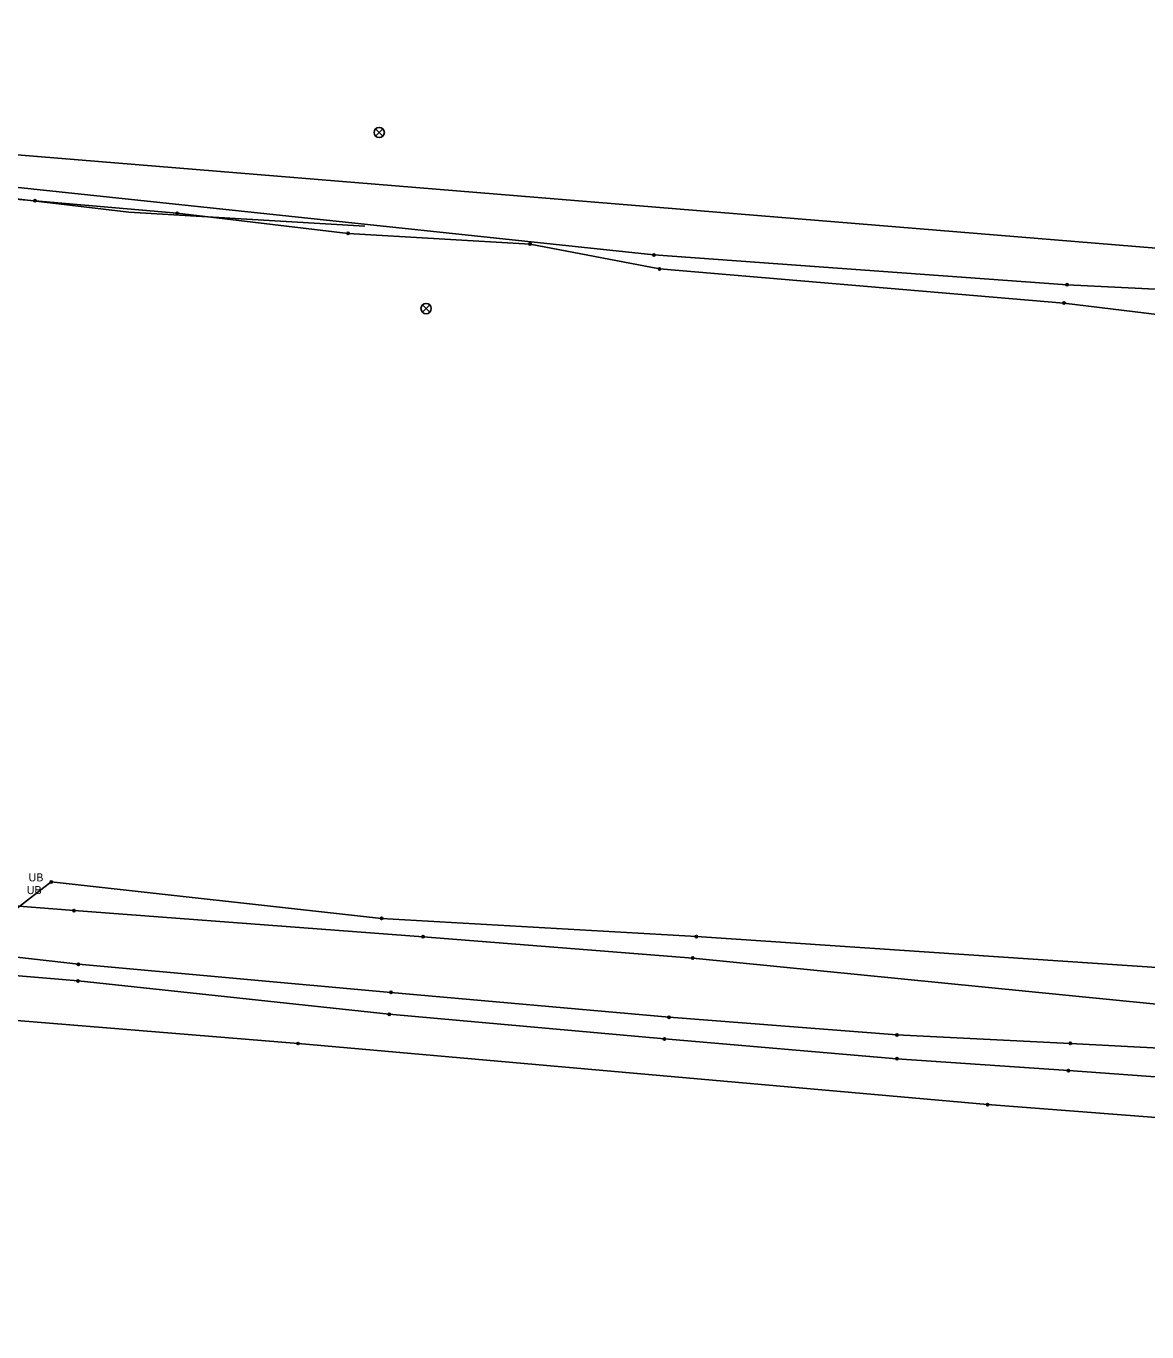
# Model space of a CAD drawing. Extents: x 20500343 to 20505311, y 7953484 to 7954193.
# Drawn here: x 20503191.9 to 20503387.9, y 7953635.3 to 7953863.5 of the extents above; entities that cross this region are included whole.
import ezdxf

# ---------------------------------------------------------------- set-up
doc = ezdxf.new("R2010")
doc.units = 0
for name, color, linetype in [('C-PROP-LINE-LOT', 7, 'Continuous'), ('V-ANNO-BNDY', 7, 'Continuous'), ('V-ANNO-NOTE', 7, 'Continuous'), ('V-SITE-FENC', 7, 'Continuous'), ('V-SSWR-STRC', 7, 'Continuous')]:
    doc.layers.add(name, color=color, linetype=linetype)

msp = doc.modelspace()

# ---------------------------------------------------------------- linework, layer by layer
at = {"layer": 'C-PROP-LINE-LOT'}
msp.add_line((20503185.95, 7953841.37), (20503437.68, 7953820.69), dxfattribs=at)
for points in [[(20502923.89, 7953863.48), (20502923.87, 7953857.22), (20502949.69, 7953853.27), (20502980.21, 7953850.33), (20503012.7, 7953848.26), (20503049, 7953845.63), (20503082.17, 7953842.1), (20503112.95, 7953839.56), (20503138.35, 7953837.73), (20503193.47, 7953832.98), (20503218.34, 7953830.79), (20503248.23, 7953827.27), (20503280.04, 7953825.39), (20503302.66, 7953821.04), (20503373.35, 7953815.08), (20503420.82, 7953809.31), (20503465.76, 7953808.12), (20503523.4, 7953802.43), (20503558.95, 7953800.72), (20503614.46, 7953794.57), (20503665.44, 7953787.94), (20503677.02, 7953787.65), (20503693.06, 7953785.61)], [(20502923.89, 7953863.47), (20502924.73, 7953858.96), (20502949.8, 7953857.13), (20502979.15, 7953855.66), (20503010.57, 7953853.39), (20503049.45, 7953848.56), (20503082.45, 7953846.12), (20503112.47, 7953843.06), (20503138.8, 7953840.76), (20503301.69, 7953823.49), (20503373.91, 7953818.29), (20503420.2, 7953815.98), (20503466.21, 7953810.37), (20503524.2, 7953805.14), (20503558.57, 7953802.46), (20503613.81, 7953798.05), (20503665.73, 7953789.96), (20503676.95, 7953790.93), (20503697.66, 7953791.85), (20503755.76, 7953785.45), (20503787.39, 7953784.49)], [(20503171.09, 7953843.45), (20503173.08, 7953837.17), (20503180.82, 7953834.4), (20503209.91, 7953830.98), (20503251.16, 7953828.52)], [(20502583.99, 7953772.95), (20502610.65, 7953768.87), (20502654.81, 7953765.56), (20502704, 7953762.66), (20502780.84, 7953747.28), (20502856.1, 7953741.6), (20502958.12, 7953733.02), (20503064.96, 7953721.73), (20503167.51, 7953711.49), (20503200.31, 7953708.91), (20503261.33, 7953704.35), (20503308.48, 7953700.62), (20503425.37, 7953689.03), (20503525.59, 7953683.92), (20503632.36, 7953675.44)], [(20502567.82, 7953767.29), (20502613.16, 7953765.86), (20502660.75, 7953761.57), (20502684.96, 7953758.32), (20502704.25, 7953752.73), (20502749.31, 7953741.65), (20502800.87, 7953733.72), (20502861.3, 7953730.84), (20502920.69, 7953724.3), (20502983.15, 7953721.6), (20503039.18, 7953715.3), (20503094.87, 7953710.44), (20503155.33, 7953704.72), (20503201.09, 7953699.55), (20503255.71, 7953694.61), (20503304.33, 7953690.28), (20503344.16, 7953687.19), (20503374.46, 7953685.7), (20503426.83, 7953682.97), (20503524.49, 7953672.95), (20503631.72, 7953664.81)], [(20502567.9, 7953761.34), (20502613.51, 7953762.6), (20502660.72, 7953759.56), (20502684.44, 7953756.31), (20502703.23, 7953750.18), (20502747.73, 7953738.37), (20502800.44, 7953730.37), (20502860.52, 7953724.51), (20502919.86, 7953720.87), (20502983.04, 7953717.79), (20503038.66, 7953709.78), (20503094.29, 7953705.56), (20503153.13, 7953700.69), (20503201.01, 7953696.62), (20503255.42, 7953690.81), (20503303.52, 7953686.48), (20503344.16, 7953683.02), (20503374.14, 7953680.96), (20503426.87, 7953677.14), (20503523.93, 7953669.23), (20503630.84, 7953663.08)], [(20502753.52, 7953725.91), (20502816.21, 7953720.99), (20502880.43, 7953715.32), (20503003.58, 7953704.35), (20503122.54, 7953695.27), (20503239.48, 7953685.69), (20503360, 7953675.01), (20503474.19, 7953666.22), (20503697.41, 7953647.35), (20503810.09, 7953637.77), (20503838.81, 7953635.29)], [(20503189.83, 7953708.93), (20503196.34, 7953713.92), (20503254.07, 7953707.55), (20503309.11, 7953704.37), (20503425.93, 7953696.5), (20503526.62, 7953689.02), (20503632.63, 7953678.56)]]:
    msp.add_lwpolyline(points, dxfattribs=at)
at = {"layer": 'V-ANNO-BNDY'}
msp.add_line((20503223.08, 7953707.22), (20503223.08, 7953707.22), dxfattribs=at)
at = {"layer": 'V-ANNO-NOTE'}
for centre in [(20503193.47, 7953832.98), (20503218.34, 7953830.79), (20503248.23, 7953827.27), (20503280.04, 7953825.39), (20503301.69, 7953823.49), (20503302.66, 7953821.04), (20503373.91, 7953818.29), (20503373.35, 7953815.08), (20503196.34, 7953713.92), (20503200.31, 7953708.91), (20503254.07, 7953707.55), (20503261.33, 7953704.35), (20503309.11, 7953704.37), (20503201.09, 7953699.55), (20503308.48, 7953700.62), (20503201.01, 7953696.62), (20503255.71, 7953694.61), (20503255.42, 7953690.81), (20503304.33, 7953690.28), (20503239.48, 7953685.69), (20503303.52, 7953686.48), (20503344.16, 7953687.19), (20503374.46, 7953685.7), (20503344.16, 7953683.02), (20503374.14, 7953680.96), (20503360, 7953675.01)]:
    msp.add_circle(centre, 0.2, dxfattribs=at)
at = {"layer": 'V-SSWR-STRC'}
for points in [[(20503253.02, 7953844.25), (20503253.66, 7953844.89), (20503253.02, 7953845.52)], [(20503254.3, 7953845.52), (20503253.66, 7953844.89), (20503254.3, 7953844.25)], [(20503261.22, 7953813.49), (20503261.86, 7953814.12), (20503261.22, 7953814.76)], [(20503262.5, 7953814.76), (20503261.86, 7953814.12), (20503262.5, 7953813.49)]]:
    msp.add_lwpolyline(points, dxfattribs=at)
for centre, start, end in [((20503253.66, 7953844.89), 135, 225), ((20503253.66, 7953844.89), 45, 135), ((20503253.66, 7953844.89), 315, 45), ((20503253.66, 7953844.89), 225, 315), ((20503261.86, 7953814.12), 135, 225), ((20503261.86, 7953814.12), 45, 135), ((20503261.86, 7953814.12), 225, 315), ((20503261.86, 7953814.12), 315, 45)]:
    msp.add_arc(centre, 0.899, start, end, dxfattribs=at)

# ---------------------------------------------------------------- texts
at = {"layer": 'V-SITE-FENC'}
for p in [(20503192.37, 7953714.02), (20503192.05, 7953711.8)]:
    msp.add_text('UB', height=1.399, dxfattribs=at).set_placement(p)

doc.saveas('drawing.dxf')
